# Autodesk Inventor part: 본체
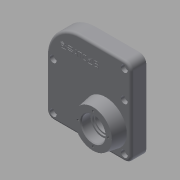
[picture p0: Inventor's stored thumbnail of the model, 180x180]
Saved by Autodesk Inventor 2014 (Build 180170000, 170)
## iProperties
Created: 2015-10
Part Number: 본체
Material: Generic
Document SubType Name: Modeling
Designer: youjin04
Density: 1 g/cm^3
Appearance: Default
Author: youjin04
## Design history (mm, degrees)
sketch "스케치1"
  geometry: L1 (-52, -63)-(32, -63); L2 (40, -55)-(40, 0); L3 (0, 40)-(-52, 40); L4 (-60, -63)-(40, 40); L5 (40, -63)-(-60, 40); L6 (-28, -63)-(-28, -59); L7 (-28, -59)-(27.528, -59); L8 (-28, -59)-(-47.528, -59); L9 (40, -35)-(36, -35); L10 (36, -35)-(36, -50.528); L11 (36, -35)-(36, -4.472); L12 (-60, -25)-(-56, -25); L13 (-56, 17)-(-56, 27.528); L14 (-56, 17)-(-56, 4.472); L15 (-56, -25)-(-56, -4.472); L16 (-56, -25)-(-56, -50.528); L17 (-30, 36)-(-47.528, 36); L18 (-30, 36)-(-17.436, 36); L19 (-17.436, 36)-(0, 36); L20 (32, -6)-(40, -6); L21 (32, 6)-(39.547, 6); L22 (-52, 6)-(-60, 6); L23 (-52, -6)-(-60, -6); L24 (-52, -49)-(-60, -49); L25 (-46, -55)-(-46, -63); L26 (-52, 26)-(-60, 26); L27 (-46, 32)-(-46, 40); L28 (26, -55)-(26, -63); L29 (32, -49)-(40, -49); C1 r 2.25 at (-52, 32); C2 r 2.25 at (-52, -55); C3 r 2.25 at (32, -55); C4 r 2.25 at (-52, 0); C5 r 2.25 at (32, 0); A1 r 8 centre (-52, 32) between (-52, 40) and (-60, 32); A2 r 8 centre (-52, -55) between (-60, -55) and (-52, -63); A3 r 8 centre (32, -55) between (32, -63) and (40, -55); A4 r 6 centre (-52, 32) between (-56, 27.528) and (-47.528, 36); A5 r 6 centre (-52, 0) between (-56, -4.472) and (-56, 4.472); A6 r 6 centre (-52, -55) between (-47.528, -59) and (-56, -50.528); A7 r 6 centre (32, -55) between (36, -50.528) and (27.528, -59); A8 r 6 centre (32, 0) between (35.688, 4.733) and (36, -4.472); A9 r 40 centre (0, 0) between (40, 0) and (0, 40); A10 r 36 centre (0, 0) between (35.688, 4.733) and (0, 36); 2 further points; 1 other entity
  constraints: 58 end point, 31 point on circle, 17 tangent, 15 centre point, 11 coincident, 11 perpendicular, 11 point on line, 6 collinear, 4 horizontal, 4 parallel, 4 vertical alignment, 3 horizontal alignment, 2 equal radius, 2 midpoint, 1 vertical, 12 other
  dimensions: "d3" = 100 distance of L5.end L4.end; "d4" = 103 distance of L4.end L5.start; "d8" = 8 radius of A1; "d9" = 4.5 diameter of C1; "d10" = 4.5 diameter of C2; "d11" = 4.5 diameter of C3; "d12" = 4.5 diameter of C4; "d14" = 4.5 diameter of C5; "d16" = 6 radius of A4; "d17" = 6 radius of A5; "d18" = 6 radius of A6; "d19" = 6 radius of A7; "d20" = 6 radius of A8; "d21" = 4 distance of L6.start L6.end; "d22" = 4 distance of L9.start L9.end; "d23" = 4 distance of L12.start L12.end
extrude "돌출2" join sketch "스케치1" distance "d24" = 18; taper "d25" = 0 deg
extrude "돌출3" join sketch "스케치1" distance "d26" = 4; taper "d27" = 0 deg
sketch "스케치2"
  geometry: L1 (-52, -63)-(32, -63) reference; L2 (-60, 32)-(-60, -55) reference; C1 r 10 at (-30, -33)
  constraints: 1 centre point
  dimensions: "d29" = 20 diameter of C1; "d30" = 30 distance from line of C1.centre L1; "d31" = 30 distance from line of C1.centre L2
extrude "돌출4" cut sketch "스케치2" distance "d32" = 4; taper "d33" = 0 deg
sketch "스케치3"
  geometry: C1 r 10 at (30, -33) reference; C2 r 25 at (30, -33)
  constraints: 1 centre point, 1 coincident
  dimensions: "d34" = 50 diameter of C2
extrude "돌출5" join sketch "스케치3" distance "d35" = 15; taper "d36" = -10 deg
sketch "스케치4"
  geometry: C1 r 22.355 at (0, 0) reference; A1 r 18 centre (0, 0) between (0, 18) and (-18, 0); 3 further points
  constraints: 4 point on circle, 1 centre point, 1 coincident
  dimensions: "d37" = 36 diameter of A1
hole "구멍1" sketch "스케치4" at (0, 18), (-18, 0), (0, -18), (18, 0) diameter "d38" = 2.459; stored, may be unused: countersink angle "d42" = 90 deg, drill point angle "d44" = 118 deg; dims "d39" = 8, "d40" = 4, "d41" = 2, "d43" = 10
sketch "스케치5"
  geometry: L1 (-40, -55)-(-40, 0) reference; L2 (52, -63)-(-32, -63) reference; L3 (60, 32)-(60, -55) reference; L4 (0, 40)-(52, 40) reference; C1 r 25 at (30, -33) reference; C2 r 2.25 at (-32, 0) reference; C3 r 2.25 at (52, 0) reference; C4 r 2.25 at (52, 32) reference; C5 r 2.25 at (-32, -55) reference; C6 r 2.25 at (52, -55) reference; A1 r 8 centre (-32, -55) between (-40, -55) and (-32, -63) reference; A2 r 8 centre (52, -55) between (52, -63) and (60, -55) reference; A3 r 8 centre (52, 32) between (60, 32) and (52, 40) reference; A4 r 40 centre (0, 0) between (0, 40) and (-40, 0) reference
fillet "모깎기1" dims "d45" = 3
fillet "모깎기2" dims "d46" = 3
sketch "스케치8"
  geometry: C1 r 1.23 at (0, -18) reference; C2 r 1.23 at (0, 18) reference; C3 r 1.23 at (-18, 0) reference; C4 r 1.23 at (18, 0) reference; C5 r 12.645 at (0, 0) reference; C6 r 22.355 at (0, 0) reference; 1 further point
sketch "스케치9"
  geometry: C1 r 10 at (-30, -33) reference; C2 r 16 at (-30, -33)
  constraints: 1 centre point, 1 coincident
  dimensions: "d52" = 32 diameter of C2
sketch "스케치11"
  geometry: C1 r 2.25 at (-32, 0) reference; C2 r 2.25 at (52, 0) reference; C3 r 2.25 at (52, 32) reference; C4 r 2.25 at (-32, -55) reference; C5 r 2.25 at (52, -55) reference; C6 r 4 at (-32, 0); C7 r 4 at (-32, -55); C8 r 4 at (52, -55); C9 r 4 at (52, 0); C10 r 4 at (52, 32); A1 r 8 centre (-32, -55) between (-40, -55) and (-32, -63) reference; A2 r 8 centre (52, -55) between (52, -63) and (60, -55) reference; A3 r 8 centre (52, 32) between (60, 32) and (52, 40) reference
  constraints: 5 centre point, 5 coincident
  dimensions: "d61" = 8 diameter of C6; "d62" = 8 diameter of C7; "d63" = 8 diameter of C8; "d64" = 8 diameter of C9; "d65" = 8 diameter of C10
extrude "돌출9" cut sketch "스케치11" distance "d66" = 4.4; taper "d67" = 0 deg
sketch "스케치12"
  geometry: C1 r 22.355 at (0, 0) reference; C2 r 14 at (0, 0); C3 r 12 at (0, 0); 1 further point
  constraints: 2 centre point, 2 coincident
  dimensions: "d68" = 28 diameter of C2; "d69" = 24 diameter of C3
extrude "돌출10" cut sketch "스케치12" distance "d70" = 13; taper "d71" = 0 deg
extrude "돌출11" cut sketch "스케치12" distance "d72" = 11; taper "d73" = 0 deg
sketch "스케치13"
  geometry: L1 (-40, -55)-(-40, 0) reference; L2 (0, 40)-(52, 40) reference; 2 further points
  constraints: 1 coincident, 1 other
  dimensions: "d74" = 40 distance from line of point (0, 20) L1; "d75" = 20 distance from line of point (0, 20) L2
feature "엠보싱1" sketch "스케치13" dims "d76" = 0.5, "d77" = 0
fillet "모깎기4" dims "d78" = 3
chamfer "모따기1" distance "d79" = 1; stored, may be unused: second distance "d80" = 2, angle "d81" = 45 deg
sketch "스케치14"
  geometry: C1 r 16 at (0, 0); C2 r 11 at (0, 0); A1 r 33 centre (0, 0) between (31.75, 8.997) and (0, 33) reference
  constraints: 2 centre point, 2 coincident
  dimensions: "d82" = 32 diameter of C1; "d83" = 22 diameter of C2
extrude "돌출12" join sketch "스케치14" distance "d84" = 9; taper "d85" = 0 deg
fillet "모깎기5" dims "d86" = 3
extrude "돌출13" join sketch "스케치9" distance "d87" = 9; taper "d88" = 0 deg
chamfer "모따기2" distance "d89" = 1; stored, may be unused: second distance "d90" = 2, angle "d91" = 45 deg
sketch "스케치15"
  geometry: C1 r 16 at (0, 0) reference; C2 r 11 at (0, 0) reference; 1 further point
node "솔리드1"
other parameters: "d5" = 36
